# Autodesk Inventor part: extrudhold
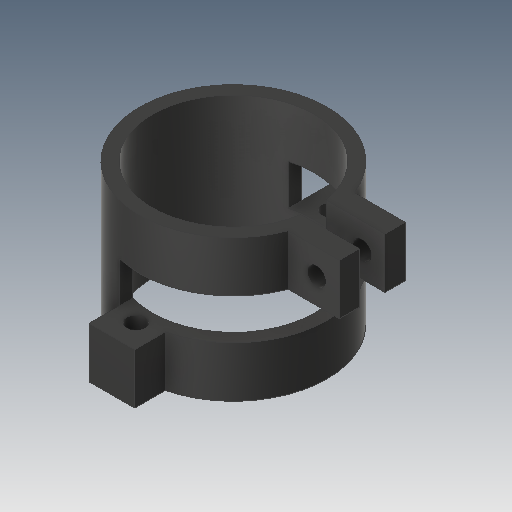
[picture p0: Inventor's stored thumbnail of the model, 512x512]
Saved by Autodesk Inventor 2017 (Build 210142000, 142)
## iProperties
Created: 2018-08
Part Number: extrudhold
Material: Plastic, Opaque Black
Document SubType Name: Modeling
Designer: JK
Density: 0.952 g/cm^3
Appearance: Smooth - Black
Author: JK
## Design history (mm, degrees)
sketch "Sketch1"
  geometry: C1 r 15.5 at (0, 0); C2 r 18.5 at (0, 0); 1 further point
  constraints: 2 centre point, 2 coincident
  dimensions: "d0" = 31 diameter of C1; "d1" = 37 diameter of C2
extrude "Extrusion1" new body sketch "Sketch1" distance "d2" = 10; taper "d3" = 0 deg
sketch "Sketch2"
  geometry: L1 (4.5, -14.832)-(4.5, -24); L2 (4.5, -24)-(-4.5, -24); L3 (-4.5, -24)-(-4.5, -14.832); L4 (4.5, 14.832)-(4.5, 24); L5 (4.5, 24)-(-4.5, 24); L6 (-4.5, 24)-(-4.5, 14.832); A1 r 15.5 centre (0, 0) between (-4.5, -14.832) and (-4.5, 14.832) reference; A2 r 15.5 centre (0, 0) between (-4.5, -14.832) and (4.5, -14.832); A3 r 15.5 centre (0, 0) between (4.5, 14.832) and (-4.5, 14.832); 1 further point
  constraints: 12 end point, 6 point on circle, 2 centre point, 2 parallel, 1 concentric, 1 point on line
  dimensions: "d4" = 9 distance between parallel lines of L1 L3; "d5" = 9 distance between parallel lines of L6 L4; "d6" = 4.5 distance from line of point (0, 0) L3; "d8" = 48 distance between parallel lines of L5 L2; "d9" = 24 distance from line of point (0, 0) L2
extrude "Extrusion2" join sketch "Sketch2" distance "d10" = 10; taper "d11" = 0 deg
sketch "Sketch3"
  geometry: C1 r 1.85 at (0, -19.25); C2 r 1.85 at (0, 19.25); 1 further point
  constraints: 2 centre point
  dimensions: "d12" = 3.7 diameter of C1; "d13" = 38.5 distance of C2.centre C1.centre; "d14" = 19.25 distance of point (0, 0) C1.centre
extrude "Extrusion3" cut sketch "Sketch3" distance "d15" = 10; taper "d16" = 0 deg
sketch "Sketch5"
  geometry: L1 (-4.5, -17.944)-(-4.5, -24) reference; L2 (-4.5, -17.944)-(-4.5, -14.832); L3 (-4.5, 17.944)-(-4.5, 14.832); A1 r 15.5 centre (0, 0) between (-4.5, 14.832) and (-4.5, -14.832); A2 r 18.5 centre (0, 0) between (-4.5, 17.944) and (-4.5, -17.944); A3 r 18.5 centre (0, 0) between (-4.5, 17.944) and (-4.5, -17.944) reference; 2 further points
  constraints: 4 end point, 4 point on circle, 2 centre point, 2 coincident, 1 collinear, 1 vertical, 2 other
extrude "Extrusion4" join sketch "Sketch5" distance "d19" = 8; taper "d20" = 0 deg
sketch "Sketch6"
  geometry: C1 r 15.5 at (0, 0); C2 r 18.5 at (0, 0); A1 r 15.5 centre (0, 0) between (-4.5, 14.832) and (-4.5, -14.832) reference; 1 further point
  constraints: 2 centre point, 1 coincident, 1 concentric
  dimensions: "d21" = 31 diameter of C1
extrude "Extrusion5" join sketch "Sketch6" distance "d22" = 10; taper "d23" = 0 deg
sketch "Sketch7"
  geometry: L1 (5.524, -1.5)-(22.142, -1.5); L2 (22.142, -1.5)-(22.142, 1.5); L3 (22.142, 1.5)-(5.524, 1.5); L4 (5.524, 1.5)-(5.524, -1.5); 1 further point
  constraints: 8 end point, 2 parallel, 1 horizontal, 1 perpendicular
  dimensions: "d24" = 3 distance of L3.end L1.start; "d25" = 1.5 distance from line of point (0, 0) L1
extrude "Extrusion6" cut sketch "Sketch7" distance "d26" = 12.25; taper "d27" = 0 deg
sketch "Sketch8"
  geometry: L1 (15.427, -1.5)-(27.427, -1.5); L2 (27.427, -1.5)-(27.427, -6.5); L3 (27.427, -6.5)-(15.427, -6.5); L4 (15.427, -6.5)-(15.427, -1.5); L5 (18.439, 1.5)-(15.427, 1.5) reference; L6 (15.427, 1.5)-(27.427, 1.5); L7 (27.427, 1.5)-(27.427, 6.5); L8 (27.427, 6.5)-(15.427, 6.5); L9 (15.427, 6.5)-(15.427, 1.5); 1 further point
  constraints: 16 end point, 4 parallel, 2 horizontal, 2 perpendicular, 1 collinear
  dimensions: "d28" = 5 distance between parallel lines of L1 L3; "d29" = 5 distance between parallel lines of L8 L6; "d30" = 12 distance of L7.end L8.end
extrude "Extrusion7" join sketch "Sketch8" distance "d31" = 10; taper "d32" = 0 deg
sketch "Sketch9"
  geometry: L1 (10.107, 0)-(10.107, -10) reference; L2 (10.107, 0)-(0, 0) reference; C1 r 1.85 at (5.607, -5); 1 further point
  constraints: 1 centre point
  dimensions: "d33" = 3.7 diameter of C1; "d34" = 4.5 distance from line of L1 C1.centre; "d35" = 5 distance from line of L2 C1.centre
extrude "Extrusion8" cut sketch "Sketch9" distance "d36" = 24.5; taper "d37" = 0 deg
sketch "Sketch10"
  geometry: L1 (27.427, -1.5)-(27.427, -6.5) reference; L2 (27.427, -2.5)-(12.843, -2.5); L3 (12.843, -2.5)-(12.843, 2.5); L4 (12.843, 2.5)-(27.427, 2.5); L5 (27.427, 2.5)-(27.427, -2.5); L6 (27.427, -1.5)-(15.427, -1.5) reference; L7 (15.427, 1.5)-(27.427, 1.5) reference; 1 further point
  constraints: 8 end point, 2 parallel, 1 horizontal, 1 perpendicular, 1 point on line
  dimensions: "d38" = 1 distance between parallel lines of L6 L2; "d39" = 1 distance between parallel lines of L7 L4
extrude "Extrusion9" cut sketch "Sketch10" distance "d40" = 11.5; taper "d41" = 0 deg
sketch "Sketch11"
  geometry: C1 r 16 at (0, 0); 1 further point
  constraints: 1 centre point, 1 coincident
  dimensions: "d42" = 32 diameter of C1
extrude "Extrusion10" cut sketch "Sketch11" distance "d43" = 59.25; taper "d44" = 0 deg
body "Solid1"
